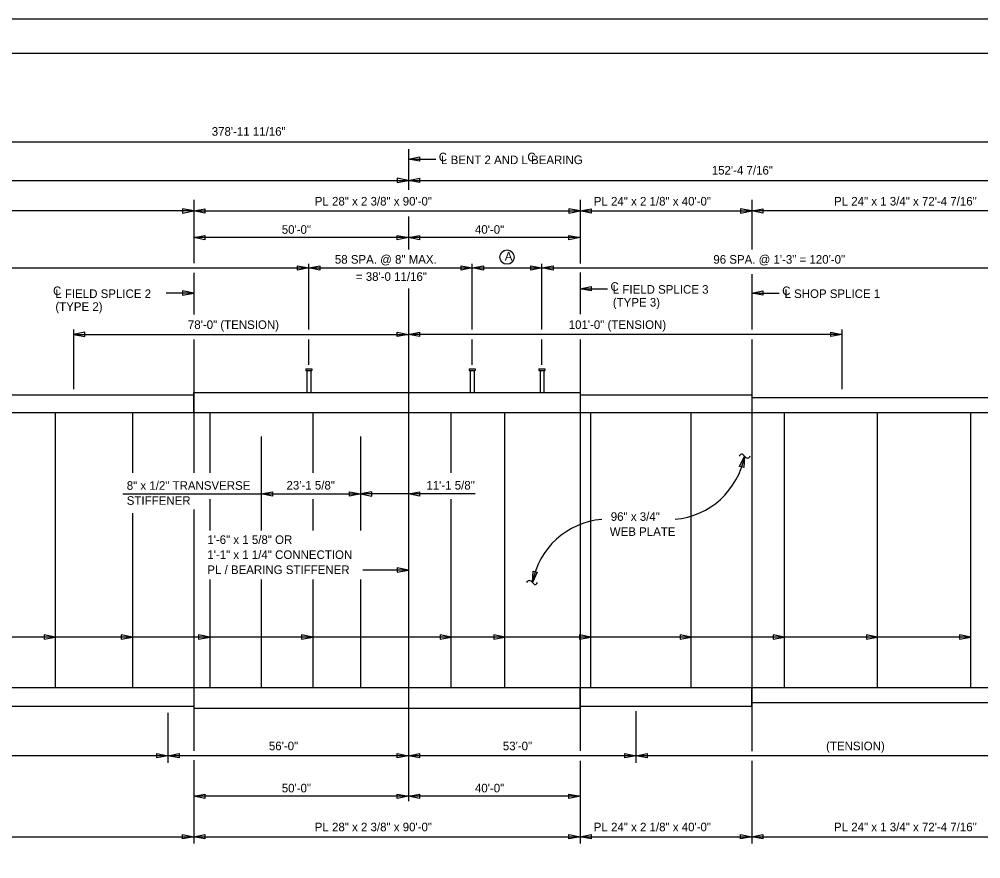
# Model space of a CAD drawing. Extents: x -305 to -161, y -187 to -99.
# Drawn here: x -249.4 to -193.4, y -148.4 to -99.5 of the extents above; entities that cross this region are included whole.
import ezdxf

# ---------------------------------------------------------------- set-up
doc = ezdxf.new("R2010")
doc.units = 0
for name, color, linetype in [('BR_AUTO DIMENSION', 7, 'Continuous'), ('BR_BORDER LINES', 7, 'Continuous'), ('BR_CENTER LINES', 7, 'Continuous'), ('BR_STRUCTURAL STEEL', 7, 'Continuous'), ('BR_TEXT', 7, 'Continuous'), ('Default', 7, 'Continuous'), ('Level 31', 7, 'Continuous')]:
    doc.layers.add(name, color=color, linetype=linetype)

msp = doc.modelspace()

# ---------------------------------------------------------------- linework, layer by layer
at = {"layer": 'BR_AUTO DIMENSION'}
for p, q in [((-284.433, -106.618), (-188.002, -106.618)), ((-226.782, -107.634), (-225.183, -107.634)), ((-284.433, -108.876), (-226.782, -108.876)), ((-226.782, -108.876), (-188.002, -108.876)), ((-239.282, -110.653), (-269.282, -110.653)), ((-239.282, -110.653), (-216.782, -110.653)), ((-216.782, -110.653), (-206.782, -110.653)), ((-188.002, -110.653), (-206.782, -110.653)), ((-226.782, -112.204), (-239.282, -112.204)), ((-216.782, -112.204), (-226.782, -112.204)), ((-282.849, -113.971), (-232.578, -113.971)), ((-232.578, -117.557), (-232.578, -113.721)), ((-232.578, -113.971), (-223.064, -113.971)), ((-223.064, -117.557), (-223.064, -113.721)), ((-223.064, -113.971), (-219.002, -113.971)), ((-219.002, -117.557), (-219.002, -113.721)), ((-219.002, -113.971), (-189.252, -113.971)), ((-216.782, -115.178), (-215.183, -115.178)), ((-239.282, -115.428), (-240.88, -115.428)), ((-206.782, -115.428), (-205.183, -115.428)), ((-246.282, -117.55), (-246.282, -121.025)), ((-201.532, -117.55), (-201.532, -121.025)), ((-246.282, -117.84), (-226.782, -117.84)), ((-232.578, -119.6), (-232.578, -118.13)), ((-201.532, -117.84), (-226.782, -117.84)), ((-223.064, -119.6), (-223.064, -118.13)), ((-219.002, -119.6), (-219.002, -118.13)), ((-243.403, -127.121), (-235.349, -127.121)), ((-235.349, -127.121), (-229.566, -127.121)), ((-226.782, -127.121), (-229.566, -127.121)), ((-222.891, -127.121), (-226.782, -127.121)), ((-226.782, -131.555), (-229.43, -131.555)), ((-194.031, -135.456), (-287.791, -135.456)), ((-240.782, -139.874), (-240.782, -142.773)), ((-213.532, -139.78), (-213.532, -142.773)), ((-240.782, -142.367), (-284.433, -142.367)), ((-226.782, -142.367), (-240.782, -142.367)), ((-213.532, -142.367), (-226.782, -142.367)), ((-188.002, -142.367), (-213.532, -142.367)), ((-226.782, -144.726), (-239.282, -144.726)), ((-216.782, -144.726), (-226.782, -144.726)), ((-269.282, -147.085), (-239.282, -147.085)), ((-239.282, -147.085), (-216.782, -147.085)), ((-216.782, -147.085), (-206.782, -147.085)), ((-206.782, -147.085), (-188.002, -147.085))]:
    msp.add_line(p, q, dxfattribs=at)
for points in [[(-226.132, -107.759), (-226.782, -107.634), (-226.132, -107.509)], [(-227.432, -109.001), (-226.782, -108.876), (-227.432, -108.751)], [(-226.132, -109.001), (-226.782, -108.876), (-226.132, -108.751)], [(-239.932, -110.778), (-239.282, -110.653), (-239.932, -110.528)], [(-238.632, -110.778), (-239.282, -110.653), (-238.632, -110.528)], [(-217.432, -110.778), (-216.782, -110.653), (-217.432, -110.528)], [(-216.132, -110.778), (-216.782, -110.653), (-216.132, -110.528)], [(-207.432, -110.778), (-206.782, -110.653), (-207.432, -110.528)], [(-206.132, -110.778), (-206.782, -110.653), (-206.132, -110.528)], [(-238.632, -112.329), (-239.282, -112.204), (-238.632, -112.079)], [(-227.432, -112.079), (-226.782, -112.204), (-227.432, -112.329)], [(-226.132, -112.329), (-226.782, -112.204), (-226.132, -112.079)], [(-217.432, -112.079), (-216.782, -112.204), (-217.432, -112.329)], [(-233.228, -113.846), (-232.578, -113.971), (-233.228, -114.096)], [(-231.928, -114.096), (-232.578, -113.971), (-231.928, -113.846)], [(-223.714, -113.846), (-223.064, -113.971), (-223.714, -114.096)], [(-222.414, -114.096), (-223.064, -113.971), (-222.414, -113.846)], [(-219.652, -113.846), (-219.002, -113.971), (-219.652, -114.096)], [(-218.352, -114.096), (-219.002, -113.971), (-218.352, -113.846)], [(-239.932, -115.553), (-239.282, -115.428), (-239.932, -115.303)], [(-216.132, -115.303), (-216.782, -115.178), (-216.132, -115.053)], [(-206.132, -115.553), (-206.782, -115.428), (-206.132, -115.303)], [(-245.632, -117.715), (-246.282, -117.84), (-245.632, -117.965)], [(-227.432, -117.715), (-226.782, -117.84), (-227.432, -117.965)], [(-226.132, -117.965), (-226.782, -117.84), (-226.132, -117.715)], [(-202.182, -117.715), (-201.532, -117.84), (-202.182, -117.965)], [(-207.488, -125.52), (-207.206, -124.922), (-207.246, -125.582)], [(-234.699, -127.246), (-235.349, -127.121), (-234.699, -126.996)], [(-230.216, -126.996), (-229.566, -127.121), (-230.216, -127.246)], [(-228.916, -126.996), (-229.566, -127.121), (-228.916, -127.246)], [(-226.132, -127.246), (-226.782, -127.121), (-226.132, -126.996)], [(-227.432, -131.68), (-226.782, -131.555), (-227.432, -131.43)], [(-219.274, -131.689), (-219.557, -132.287), (-219.516, -131.627)], [(-247.999, -135.581), (-247.349, -135.456), (-247.999, -135.331)], [(-243.499, -135.581), (-242.849, -135.456), (-243.499, -135.331)], [(-238.999, -135.581), (-238.349, -135.456), (-238.999, -135.331)], [(-232.999, -135.581), (-232.349, -135.456), (-232.999, -135.331)], [(-224.932, -135.581), (-224.282, -135.456), (-224.932, -135.331)], [(-221.807, -135.581), (-221.157, -135.456), (-221.807, -135.331)], [(-216.807, -135.581), (-216.157, -135.456), (-216.807, -135.331)], [(-210.956, -135.581), (-210.306, -135.456), (-210.956, -135.331)], [(-205.531, -135.581), (-204.881, -135.456), (-205.531, -135.331)], [(-200.106, -135.581), (-199.456, -135.456), (-200.106, -135.331)], [(-194.681, -135.581), (-194.031, -135.456), (-194.681, -135.331)], [(-241.432, -142.242), (-240.782, -142.367), (-241.432, -142.492)], [(-240.132, -142.492), (-240.782, -142.367), (-240.132, -142.242)], [(-227.432, -142.242), (-226.782, -142.367), (-227.432, -142.492)], [(-226.132, -142.492), (-226.782, -142.367), (-226.132, -142.242)], [(-214.182, -142.242), (-213.532, -142.367), (-214.182, -142.492)], [(-212.882, -142.492), (-213.532, -142.367), (-212.882, -142.242)], [(-238.632, -144.851), (-239.282, -144.726), (-238.632, -144.601)], [(-227.432, -144.601), (-226.782, -144.726), (-227.432, -144.851)], [(-226.132, -144.851), (-226.782, -144.726), (-226.132, -144.601)], [(-217.432, -144.601), (-216.782, -144.726), (-217.432, -144.851)], [(-239.932, -146.96), (-239.282, -147.085), (-239.932, -147.21)], [(-238.632, -147.21), (-239.282, -147.085), (-238.632, -146.96)], [(-217.432, -146.96), (-216.782, -147.085), (-217.432, -147.21)], [(-216.132, -147.21), (-216.782, -147.085), (-216.132, -146.96)], [(-207.432, -146.96), (-206.782, -147.085), (-207.432, -147.21)], [(-206.132, -147.21), (-206.782, -147.085), (-206.132, -146.96)]]:
    msp.add_lwpolyline(points, close=True, dxfattribs=at)
msp.add_circle((-221.033, -113.34), 0.417, dxfattribs=at)
for centre, start, end in [((-211.63, -124.118), 274.9624, 349.7037), ((-215.132, -133.091), 94.9624, 169.7037)]:
    msp.add_arc(centre, 4.497, start, end, dxfattribs=at)
at = {"layer": 'BR_BORDER LINES'}
msp.add_line((-163.178, -101.489), (-297.843, -101.489), dxfattribs=at)
at = {"layer": 'BR_CENTER LINES'}
for p, q in [((-226.782, -107.059), (-226.782, -109.43)), ((-239.282, -109.997), (-239.282, -113.69)), ((-216.782, -109.997), (-216.782, -113.711)), ((-206.782, -109.997), (-206.782, -112.903)), ((-226.782, -110.967), (-226.782, -112.903)), ((-216.782, -114.23), (-216.782, -116.66)), ((-239.282, -114.253), (-239.282, -116.675)), ((-206.782, -114.323), (-206.782, -117.557)), ((-226.782, -115.158), (-226.782, -122.412)), ((-239.282, -118.13), (-239.282, -125.898)), ((-216.782, -118.13), (-216.782, -142.086)), ((-206.782, -118.13), (-206.782, -127.661)), ((-206.782, -127.661), (-206.782, -142.108)), ((-239.282, -128.029), (-239.282, -142.086)), ((-226.782, -138.412), (-226.782, -145.014)), ((-239.282, -142.631), (-239.282, -147.486)), ((-216.782, -142.664), (-216.782, -147.486)), ((-206.782, -142.667), (-206.782, -147.486))]:
    msp.add_line(p, q, dxfattribs=at)
at = {"layer": 'BR_STRUCTURAL STEEL'}
for p, q in [((-269.282, -121.35), (-239.282, -121.35)), ((-239.282, -122.412), (-239.282, -121.225)), ((-239.282, -121.225), (-216.782, -121.225)), ((-216.782, -121.225), (-216.782, -122.412)), ((-216.782, -121.35), (-206.782, -121.35)), ((-206.782, -121.35), (-206.782, -122.412)), ((-188.002, -121.537), (-206.782, -121.537)), ((-188.002, -122.412), (-284.433, -122.412)), ((-247.349, -122.412), (-247.349, -138.412)), ((-242.849, -122.412), (-242.849, -125.898)), ((-238.349, -122.412), (-238.349, -125.898)), ((-232.349, -122.412), (-232.349, -125.898)), ((-226.782, -122.412), (-226.782, -138.412)), ((-224.282, -125.898), (-224.282, -122.412)), ((-221.157, -138.412), (-221.157, -122.412)), ((-216.157, -138.412), (-216.157, -122.412)), ((-210.306, -138.412), (-210.306, -122.412)), ((-204.881, -138.412), (-204.881, -122.412)), ((-199.456, -138.412), (-199.456, -122.412)), ((-194.031, -138.412), (-194.031, -122.412)), ((-235.349, -123.779), (-235.349, -129.248)), ((-229.566, -123.779), (-229.566, -129.248)), ((-238.349, -127.432), (-238.349, -129.248)), ((-232.349, -127.432), (-232.349, -129.248)), ((-224.282, -138.412), (-224.282, -127.432)), ((-242.849, -128.238), (-242.849, -138.412)), ((-238.349, -132.117), (-238.349, -138.412)), ((-235.349, -132.117), (-235.349, -138.412)), ((-232.349, -132.117), (-232.349, -138.412)), ((-229.566, -132.117), (-229.566, -138.412)), ((-188.002, -138.412), (-284.433, -138.412)), ((-239.282, -138.412), (-239.282, -139.6)), ((-216.782, -139.6), (-216.782, -138.412)), ((-206.782, -139.475), (-206.782, -138.412)), ((-188.002, -139.287), (-206.782, -139.287)), ((-269.282, -139.475), (-239.282, -139.475)), ((-239.282, -139.6), (-216.782, -139.6)), ((-216.782, -139.475), (-206.782, -139.475))]:
    msp.add_line(p, q, dxfattribs=at)
at = {"layer": 'BR_TEXT'}
for p, q in [((-207.466, -124.869), (-207.508, -124.93)), ((-207.124, -124.996), (-207.287, -124.847)), ((-206.891, -124.93), (-206.92, -124.976)), ((-219.872, -132.279), (-219.842, -132.233)), ((-219.638, -132.213), (-219.475, -132.362)), ((-219.297, -132.34), (-219.255, -132.279))]:
    msp.add_line(p, q, dxfattribs=at)
for centre, radius, start, end in [((-207.368, -124.922), 0.111, 43.4519, 151.7375), ((-207.03, -124.915), 0.125, 221.007, 330.8059), ((-219.732, -132.294), 0.125, 41.007, 150.8059), ((-219.395, -132.287), 0.111, 223.4519, 331.7375)]:
    msp.add_arc(centre, radius, start, end, dxfattribs=at)
at = {"layer": 'Default'}
for p, q in [((-232.75, -119.85), (-232.75, -119.944)), ((-232.75, -119.85), (-232.407, -119.85)), ((-232.75, -119.944), (-232.407, -119.944)), ((-232.688, -119.944), (-232.688, -121.225)), ((-232.469, -119.944), (-232.469, -121.225)), ((-232.407, -119.85), (-232.407, -119.944)), ((-223.236, -119.85), (-223.236, -119.944)), ((-223.236, -119.85), (-222.892, -119.85)), ((-223.236, -119.944), (-222.892, -119.944)), ((-223.173, -119.944), (-223.173, -121.225)), ((-222.955, -119.944), (-222.955, -121.225)), ((-222.892, -119.85), (-222.892, -119.944)), ((-219.173, -119.85), (-219.173, -119.944)), ((-219.173, -119.85), (-218.83, -119.85)), ((-219.173, -119.944), (-218.83, -119.944)), ((-219.111, -119.944), (-219.111, -121.225)), ((-218.892, -119.944), (-218.892, -121.225)), ((-218.83, -119.85), (-218.83, -119.944))]:
    msp.add_line(p, q, dxfattribs=at)
at = {"layer": 'Level 31'}
msp.add_lwpolyline([(-305.176, -187.489), (-161.176, -187.489), (-161.176, -99.489), (-305.176, -99.489)], close=True, dxfattribs=at)

# ---------------------------------------------------------------- texts
at = {"layer": 'BR_AUTO DIMENSION'}
for s, p in [('378\'-11 11/16"', (-238.233, -106.272)), ('152\'-4 7/16"', (-209.111, -108.53)), ('PL 28" x 2 3/8" x 90\'-0"', (-232.23, -110.334)), ('PL 24" x 2 1/8" x 40\'-0"', (-215.98, -110.334)), ('PL 24" x 1 3/4" x 72\'-4 7/16"', (-201.99, -110.334)), ('50\'-0"', (-234.153, -111.979)), ('40\'-0"', (-222.903, -111.979)), ('A', (-221.167, -113.543)), (' 101\'-0" (TENSION)', (-217.629, -117.521)), ('96" x 3/4" ', (-214.991, -128.694)), ('WEB PLATE', (-215.049, -129.569)), ('56\'-0"', (-234.903, -142.048)), ('(TENSION)', (-202.453, -142.048)), ('50\'-0"', (-234.153, -144.501)), ('40\'-0"', (-222.903, -144.501)), ('PL 28" x 2 3/8" x 90\'-0"', (-232.23, -146.766)), ('PL 24" x 2 1/8" x 40\'-0"', (-215.98, -146.766)), ('PL 24" x 1 3/4" x 72\'-4 7/16"', (-201.99, -146.766))]:
    msp.add_text(s, height=0.5, rotation=360, dxfattribs=at).set_placement(p)
for s, p in [('58 SPA. @ 8" MAX.', (-231.061, -113.721)), ('96 SPA. @ 1\'-3" = 120\'-0"', (-209.018, -113.721)), ('= 38\'-0 11/16"', (-229.837, -114.721)), (' 78\'-0" (TENSION)', (-239.806, -117.521)), ('23\'-1 5/8"', (-233.878, -126.871)), ('11\'-1 5/8"', (-225.732, -126.871)), ('53\'-0"', (-221.278, -142.048))]:
    msp.add_text(s, height=0.5, dxfattribs=at).set_placement(p)
at = {"layer": 'BR_TEXT'}
for s, p in [('C', (-225.009, -107.758)), ('L BENT 2 AND L BEARING', (-224.874, -107.924)), ('C', (-219.849, -107.758)), ('C', (-215.009, -115.301)), ('C', (-247.474, -115.551)), ('L FIELD SPLICE 2', (-247.339, -115.718)), ('L FIELD SPLICE 3', (-214.874, -115.468)), ('C', (-205.009, -115.551)), ('L SHOP SPLICE 1', (-204.874, -115.718)), ('(TYPE 3)', (-214.874, -116.218)), ('(TYPE 2)', (-247.339, -116.468)), ('8" x 1/2" TRANSVERSE ', (-243.181, -126.885)), ('STIFFENER', (-243.181, -127.76)), ('1\'-6" x 1 5/8" OR', (-238.49, -130.038)), ('1\'-1" x 1 1/4" CONNECTION ', (-238.49, -130.913)), ('PL / BEARING STIFFENER', (-238.49, -131.788))]:
    msp.add_text(s, height=0.5, rotation=360, dxfattribs=at).set_placement(p)

doc.saveas('drawing.dxf')
